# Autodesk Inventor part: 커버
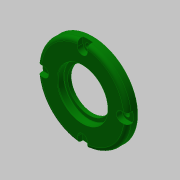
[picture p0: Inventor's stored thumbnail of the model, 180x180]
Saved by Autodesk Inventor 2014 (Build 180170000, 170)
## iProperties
Created: 2019-05
Part Number: 커버
Material: 알루미늄 6061
Document SubType Name: Modeling
Designer: mduedu
Density: 1 g/cm^3
Appearance: Dark Green
Author: mduedu
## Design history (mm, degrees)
sketch "스케치1"
  geometry: L1 (0, 0)-(36, 0); L2 (36, 0)-(36, -8); L3 (36, -8)-(0, -8); L4 (0, -8)-(0, 0); L5 (0, -8)-(26, -8); L6 (26, -8)-(26, -12); L7 (26, -12)-(0, -12); L8 (0, -12)-(0, -8)
  constraints: 16 end point, 4 parallel, 2 horizontal, 2 perpendicular
  dimensions: "d0" = 72 diameter of L2 L4; "d2" = 52 diameter of L6 L8; "d3" = 12 distance between parallel lines of L7 L1; "d4" = 4 distance between parallel lines of L7 L3
revolve "회전1" sketch "스케치1" stored, may be unused: angle "d5" = 90 deg
sketch "스케치2" dims "d6" = 62
  geometry: L1 (-4, 31)-(-4, 35.777); L2 (4, 31)-(4, 35.777); A1 r 4 centre (0, 31) between (-4, 31) and (4, 31); A2 r 36 centre (0, 0) between (-4, 35.777) and (4, 35.777) reference; A3 r 36 centre (0, 0) between (4, 35.777) and (-4, 35.777); 2 further points
  constraints: 6 point on circle, 4 end point, 2 centre point, 2 coincident, 2 tangent, 2 vertical alignment, 1 parallel, 1 vertical, 2 other
  dimensions: "d7" = 8 distance between parallel lines of L2 L1
extrude "돌출1" cut sketch "스케치2" distance "d8" = 4.4; taper "d9" = 0 deg
fillet "모깎기1" dims "d13" = 3
sketch "스케치3"
  geometry: L1 (36, -4.4)-(36, -8) reference; L2 (36, -8)-(26, -8) reference; L3 (26, -8)-(26, -12) reference; L4 (26, -12)-(-26, -12) reference; L5 (-26, -12)-(-26, -8) reference; L6 (-26, -8)-(-36, -8) reference; L7 (-36, -8)-(-36, -4.4) reference; L8 (-36, -4.4)-(-27, -4.4) reference; L9 (-27, -4.4)-(-27, 0) reference; L10 (-27, 0)-(27, 0) reference; L11 (27, 0)-(27, -4.4) reference; L12 (27, -4.4)-(36, -4.4) reference; L13 (0, 0)-(20, 0); L14 (20, 0)-(20, -5.2); L15 (20, -5.2)-(0, -5.2); L16 (0, -5.2)-(0, 0); L17 (0, -5.2)-(17, -5.2); L18 (17, -5.2)-(17, -8); L19 (17, -8)-(0, -8); L20 (0, -8)-(0, -5.2); L21 (0, -8)-(23, -8); L22 (23, -8)-(23, -12); L23 (23, -12)-(0, -12); L24 (0, -12)-(0, -8)
  constraints: 24 end point, 6 parallel, 3 horizontal, 3 perpendicular, 1 point on line
  dimensions: "d14" = 40 diameter of L14 L16; "d16" = 5.2 distance of L13.end L14.end; "d17" = 46 diameter of L22 L24; "d18" = 4 distance of L21.end L22.end; "d19" = 34 diameter of L18 L20
revolve "회전2" sketch "스케치3" stored, may be unused: angle "d20" = 90 deg
chamfer "모따기1" distance "d21" = 0.5; stored, may be unused: second distance "d22" = 2, angle "d23" = 30 deg
fillet "모깎기2" dims "d24" = 0.2
fillet "모깎기3" dims "d25" = 3
chamfer "모따기2" distance "d26" = 1; stored, may be unused: second distance "d27" = 2, angle "d28" = 30 deg
sketch "스케치4" dims "d29" = 62
  geometry: 6 further points
  constraints: 2 vertical alignment, 1 coincident, 7 other
  dimensions: "d32" = 360 deg dimension on point (0, 0) point (0, 31) (derived)
sketch "스케치5"
  geometry: 4 further points
  constraints: 4 other
hole "구멍1" sketch "스케치5" at (-31, 0), (0, -31), (31, 0), (0, 31) diameter "d34" = 4.5; stored, may be unused: countersink angle "d38" = 90 deg, drill point angle "d40" = 0 deg; dims "d35" = 6, "d36" = 4, "d37" = 2, "d39" = 8
node "솔리드1"
pattern_circular "원형 패턴1" dims angle "d11" = 360 deg
node "절단 모서리 투영1"
